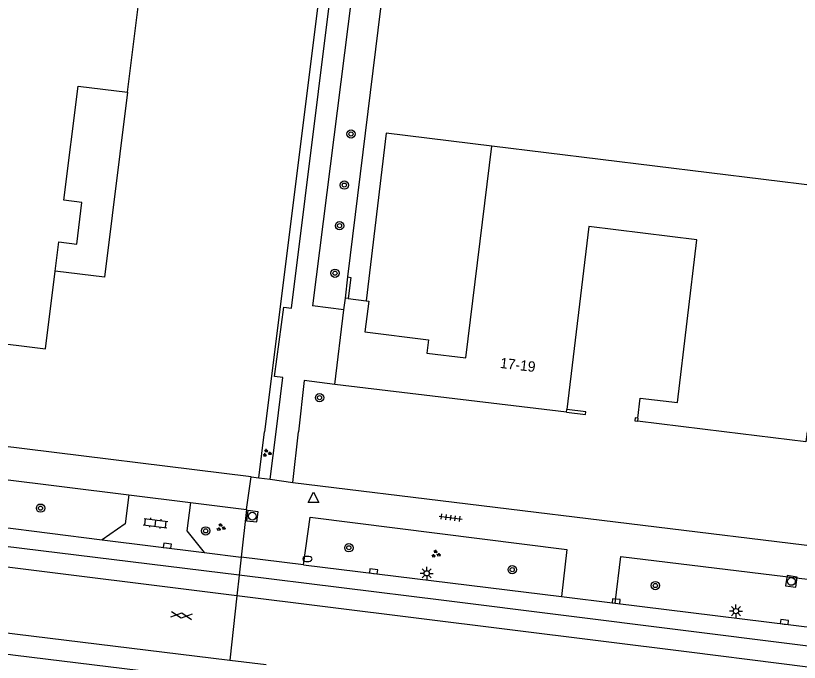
# Model space of a CAD drawing. Extents: x 131000 to 133014, y 396499 to 399001.
# Drawn here: x 131900.8 to 131976.4, y 396977.8 to 397040.1 of the extents above; entities that cross this region are included whole.
import ezdxf

# ---------------------------------------------------------------- set-up
doc = ezdxf.new("R2010")
doc.units = 0
for name, color, linetype in [('gg-afsc-hekwerk', 7, 'Continuous'), ('gg-afsc-muur', 7, 'Continuous'), ('gg-anno-huisnummerreeks BGT', 7, 'Continuous'), ('gg-bbg-gedigitaliseerde bebouwing', 7, 'Continuous'), ('gg-bbg-hoofdgebouw', 7, 'Continuous'), ('gg-bbg-luifel en loopbrug', 7, 'Continuous'), ('gg-knt-verharding', 7, 'Continuous'), ('gg-knt-verharding nz', 7, 'Continuous'), ('gt-grn-vlakafsluiter', 7, 'Continuous'), ('gt-grn-weggrens', 7, 'Continuous'), ('gt-symb-boom', 7, 'Continuous'), ('gt-symb-brandkraan', 7, 'Continuous'), ('gt-symb-gesloten verharding', 7, 'Continuous'), ('gt-symb-groenvak', 7, 'Continuous'), ('gt-symb-klinker verharding', 7, 'Continuous'), ('gt-symb-kolk', 7, 'Continuous'), ('gt-symb-lichtmast', 7, 'Continuous'), ('gt-symb-rioolschacht', 7, 'Continuous'), ('gt-symb-tegel verharding', 7, 'Continuous'), ('gt-symb-waterafsluiter', 7, 'Continuous')]:
    doc.layers.add(name, color=color, linetype=linetype)

# ---------------------------------------------------------------- blocks, each defined once
blk = doc.blocks.new('gt0-BOOM')
at = {"layer": 'gt-symb-boom'}
for radius in [0.4, 0.2]:
    blk.add_circle((0, 0), radius, dxfattribs=at)
blk = doc.blocks.new('gt0-WAFSL')
at = {"layer": 'gt-symb-waterafsluiter'}
for p, q in [((-0.5, -0.333), (0, 0.667)), ((0, 0.667), (0.5, -0.333)), ((0.5, -0.333), (-0.5, -0.333))]:
    blk.add_line(p, q, dxfattribs=at)
blk = doc.blocks.new('gt0-GRVAK')
at = {"layer": 'gt-symb-groenvak'}
for p, q in [((-0.11, 0.189), (-0.228, 0.24)), ((-0.182, 0.153), (0.088, 0.153)), ((-0.091, 0.211), (-0.156, 0.322)), ((-0.047, 0.214), (-0.047, 0.393)), ((-0.004, 0.211), (0.061, 0.322)), ((0.015, 0.189), (0.133, 0.24)), ((0.262, -0.052), (0.197, 0.059)), ((0.305, -0.049), (0.305, 0.13)), ((0.349, -0.052), (0.414, 0.059)), ((-0.245, -0.228), (-0.363, -0.177)), ((-0.318, -0.264), (-0.047, -0.264)), ((-0.226, -0.206), (-0.291, -0.095)), ((-0.183, -0.203), (-0.183, -0.024)), ((-0.139, -0.206), (-0.074, -0.095)), ((-0.12, -0.228), (-0.002, -0.177)), ((0.243, -0.074), (0.125, -0.023)), ((0.17, -0.11), (0.441, -0.11)), ((0.368, -0.074), (0.486, -0.023))]:
    blk.add_line(p, q, dxfattribs=at)
blk = doc.blocks.new('gt0-KL1')
at = {"layer": 'gt-symb-klinker verharding'}
for p, q in [((-1.15, 0.3), (1.15, 0.3)), ((-1, -0.3), (-1, 0.3)), ((-0.5, 0.3), (-0.5, 0.45)), ((0, -0.3), (0, 0.3)), ((0.5, 0.3), (0.5, 0.45)), ((1, -0.3), (1, 0.3)), ((-1.15, -0.3), (1.15, -0.3)), ((-0.5, -0.45), (-0.5, -0.3)), ((0.5, -0.45), (0.5, -0.3))]:
    blk.add_line(p, q, dxfattribs=at)
blk = doc.blocks.new('gt0-RS')
at = {"layer": 'gt-symb-rioolschacht'}
blk.add_lwpolyline([(-0.5, -0.5), (0.5, -0.5), (0.5, 0.5), (-0.5, 0.5)], close=True, dxfattribs=at)
blk.add_circle((0, 0), 0.375, dxfattribs=at)
blk = doc.blocks.new('gt0-KOLK')
at = {"layer": 'gt-symb-kolk'}
blk.add_lwpolyline([(0, 0), (0.375, 0), (0.375, 0.4), (-0.375, 0.4), (-0.375, 0), (0, 0)], dxfattribs=at)
blk = doc.blocks.new('gt0-LMAST')
at = {"layer": 'gt-symb-lichtmast'}
for p, q in [((-0.182, 0.173), (-0.447, 0.438)), ((-0.005, 0.246), (-0.005, 0.621)), ((0.172, 0.173), (0.437, 0.438)), ((-0.255, -0.004), (-0.63, -0.004)), ((-0.182, -0.181), (-0.447, -0.446)), ((-0.005, -0.254), (-0.005, -0.629)), ((0.437, -0.446), (0.172, -0.181)), ((0.245, -0.004), (0.62, -0.004))]:
    blk.add_line(p, q, dxfattribs=at)
blk.add_circle((-0.005, -0.004), 0.25, dxfattribs=at)
blk = doc.blocks.new('gt0-BR')
at = {"layer": 'gt-symb-brandkraan'}
for centre, radius, start, end in [((-0.244, 0), 0.206, 107.56694, 252.43307), ((0.599, -2.664), 3, 106.89205, 107.56694), ((0, -0.691), 0.938, 73.10799, 106.89205), ((-0.599, -2.664), 3, 72.43309, 73.10799), ((0.244, 0), 0.206, 287.56695, 72.43309), ((0.599, 2.664), 3, 252.43307, 253.10797), ((0, 0.691), 0.938, 253.10797, 286.89206), ((-0.599, 2.664), 3, 286.89206, 287.56695)]:
    blk.add_arc(centre, radius, start, end, dxfattribs=at)
blk = doc.blocks.new('gt0-TEG1')
at = {"layer": 'gt-symb-tegel verharding'}
for p, q in [((-1.125, 0), (1.125, 0)), ((-0.9, -0.25), (-0.9, 0.25)), ((-0.45, -0.25), (-0.45, 0.25)), ((0, -0.25), (0, 0.25)), ((0.45, -0.25), (0.45, 0.25)), ((0.9, -0.25), (0.9, 0.25))]:
    blk.add_line(p, q, dxfattribs=at)
blk = doc.blocks.new('gt0-GESVH1')
at = {"layer": 'gt-symb-gesloten verharding'}
for p, q in [((-0.992, -0.261), (0.008, 0.239)), ((0.008, -0.261), (-0.992, 0.239)), ((0.008, 0.239), (1.008, -0.261)), ((1.008, 0.239), (0.008, -0.261))]:
    blk.add_line(p, q, dxfattribs=at)

msp = doc.modelspace()

# ---------------------------------------------------------------- linework, layer by layer
at = {"layer": 'gg-afsc-hekwerk'}
msp.add_line((131932.903, 397064.446), (131924.856, 397000), dxfattribs=at)
msp.add_lwpolyline([(131932.89, 397014.92), (131939.73, 397070.642), (131951.59, 397069.215)], dxfattribs=at)
at = {"layer": 'gg-afsc-muur'}
for p, q in [((131932.641, 397012.873), (131932.89, 397014.92)), ((131953.989, 397001.877), (131955.8, 397001.66)), ((131960.56, 397001.06), (131960.818, 397001.028))]:
    msp.add_line(p, q, dxfattribs=at)
for points in [[(131946.783, 397027.529), (131936.59, 397028.78), (131934.65, 397012.63)], [(131932.89, 397014.92), (131933.16, 397014.88), (131932.91, 397012.84)], [(131955.8, 397001.66), (131955.83, 397001.92), (131954.02, 397002.14)], [(131960.85, 397001.29), (131960.59, 397001.32), (131960.56, 397001.06)]]:
    msp.add_lwpolyline(points, dxfattribs=at)
at = {"layer": 'gg-bbg-gedigitaliseerde bebouwing'}
for p, q in [((131980.064, 397023.446), (131946.783, 397027.529)), ((131932.91, 397012.84), (131934.65, 397012.63))]:
    msp.add_line(p, q, dxfattribs=at)
msp.add_lwpolyline([(131934.65, 397012.63), (131934.892, 397012.601), (131934.534, 397009.618), (131940.655, 397008.861), (131940.497, 397007.58), (131944.261, 397007.115), (131946.783, 397027.529)], dxfattribs=at)
at = {"layer": 'gg-bbg-hoofdgebouw'}
for p, q in [((131932.506, 397011.761), (131932.641, 397012.873)), ((131932.91, 397012.84), (131932.641, 397012.873)), ((131931.63, 397004.55), (131932.506, 397011.761)), ((131953.989, 397001.877), (131931.63, 397004.55)), ((131953.989, 397001.877), (131954.02, 397002.14)), ((131960.85, 397001.29), (131960.818, 397001.028)), ((131969.176, 397000), (131960.818, 397001.028))]:
    msp.add_line(p, q, dxfattribs=at)
for points in [[(131911.63, 397032.73), (131913.487, 397047.686), (131891.352, 397050.438)], [(131889.494, 397035.473), (131886.349, 397010.134), (131903.709, 397007.978), (131904.641, 397015.484)], [(131904.641, 397015.484), (131904.992, 397018.309), (131906.729, 397018.093), (131907.228, 397022.112), (131905.491, 397022.328), (131906.857, 397033.323), (131911.63, 397032.73)], [(131960.85, 397001.29), (131961.08, 397003.23), (131964.67, 397002.8), (131966.55, 397018.49), (131956.13, 397019.78), (131954.02, 397002.14)], [(131977.179, 397000), (131977.06, 396999.03), (131969.176, 397000)]]:
    msp.add_lwpolyline(points, dxfattribs=at)
at = {"layer": 'gg-bbg-luifel en loopbrug'}
msp.add_lwpolyline([(131911.63, 397032.73), (131909.416, 397014.891), (131904.641, 397015.484)], dxfattribs=at)
at = {"layer": 'gg-knt-verharding'}
for p, q in [((131937.41, 397075.26), (131929.484, 397012.14)), ((131932.506, 397011.761), (131929.484, 397012.14)), ((131928.666, 397004.922), (131928.111, 397000)), ((131931.63, 397004.55), (131928.666, 397004.922)), ((131828.419, 396999.672), (131909.195, 396989.576)), ((131862.805, 397000), (131911.744, 396993.913)), ((131923.541, 396995.659), (131888.328, 397000)), ((131925.4, 396995.43), (131925.96, 397000)), ((131927.56, 396995.11), (131928.111, 397000)), ((131923.541, 396995.659), (131924.309, 396995.564)), ((131924.309, 396995.564), (131925.4, 396995.43)), ((131925.4, 396995.43), (131927.56, 396995.11)), ((131927.56, 396995.11), (132000, 396986.292)), ((131911.744, 396993.913), (131917.698, 396993.172)), ((131917.698, 396993.172), (131923.1, 396992.5)), ((131923.1, 396992.5), (131922.589, 396987.915)), ((131909.195, 396989.576), (131919.015, 396988.358)), ((131919.015, 396988.358), (131922.589, 396987.915)), ((131928.599, 396987.171), (131922.589, 396987.915)), ((131928.599, 396987.171), (131953.479, 396984.104)), ((131953.479, 396984.104), (131958.659, 396983.465)), ((131958.659, 396983.465), (132000, 396978.368))]:
    msp.add_line(p, q, dxfattribs=at)
for points in [[(131925.96, 397000), (131926.6, 397005.22), (131925.81, 397005.32), (131926.69, 397012.01), (131927.45, 397011.91), (131933.966, 397064.314)], [(131911.744, 396993.913), (131911.397, 396991.114), (131909.195, 396989.576)], [(131917.698, 396993.172), (131917.358, 396990.427), (131919.015, 396988.358)], [(131928.599, 396987.171), (131929.25, 396991.77), (131954, 396988.65), (131953.479, 396984.104)], [(131958.659, 396983.465), (131959.22, 396987.96), (132000, 396983.02)]]:
    msp.add_lwpolyline(points, dxfattribs=at)
at = {"layer": 'gg-knt-verharding nz'}
msp.add_line((131921.481, 396977.976), (131924.986, 396977.548), dxfattribs=at)
for points in [[(131922.171, 396984.164), (131898.194, 396987.151), (131862.262, 396991.482), (131823.017, 396996.367), (131803.043, 396998.92), (131781.203, 397001.525), (131759.597, 397004.251), (131755.251, 397005.141), (131750.751, 397007.092), (131748.18, 397008.55), (131746.638, 397009.699)], [(131922.392, 396986.15), (131897.976, 396989.158), (131836.059, 396996.94), (131797.554, 397001.628), (131777.007, 397004.104), (131771.251, 397004.913), (131759.884, 397006.448), (131757.887, 397007.264), (131754.525, 397008.749)], [(131755.156, 396994.911), (131758.182, 396996.495), (131761.757, 396997.541), (131764.496, 396997.743), (131784.093, 396995.032), (131839.381, 396988.347), (131854.836, 396986.329), (131886.556, 396982.245), (131921.481, 396977.976)], [(131767.81, 396993.27), (131768.344, 396993.815), (131769.238, 396994.276), (131771.347, 396994.67), (131773.553, 396994.549), (131799.945, 396991.109), (131822.436, 396988.391), (131861.106, 396983.598), (131900.833, 396978.466), (131924.741, 396975.54)], [(132038.637, 396972.582), (132023.49, 396973.537), (132014.049, 396974.74), (131998.825, 396976.619), (131942.145, 396983.717), (131922.392, 396986.15)], [(132051.979, 396970.928), (132041.794, 396970.287), (132038.699, 396970.35), (132035.212, 396970.619), (132028.738, 396971.235), (132023.293, 396971.591), (131991.768, 396975.47), (131965.807, 396978.729), (131922.171, 396984.164)]]:
    msp.add_lwpolyline(points, dxfattribs=at)
at = {"layer": 'gt-grn-vlakafsluiter'}
msp.add_line((131924.309, 396995.564), (131924.856, 397000), dxfattribs=at)
at = {"layer": 'gt-grn-weggrens'}
for p, q in [((131923.1, 396992.5), (131923.541, 396995.659)), ((131922.589, 396987.915), (131922.392, 396986.15)), ((131922.392, 396986.15), (131922.171, 396984.164)), ((131922.171, 396984.164), (131921.481, 396977.976))]:
    msp.add_line(p, q, dxfattribs=at)

# ---------------------------------------------------------------- block references
at = {"layer": 'gt-symb-boom'}
for p in [(131933.188, 397028.704), (131932.538, 397023.778), (131932.079, 397019.859), (131931.639, 397015.282), (131930.149, 397003.278), (131903.233, 396992.627), (131919.167, 396990.435), (131932.979, 396988.809), (131948.738, 396986.7), (131962.549, 396985.163)]:
    msp.add_blockref('gt0-BOOM', p, dxfattribs=at)
at = {"layer": 'gt-symb-brandkraan'}
msp.add_blockref('gt0-BR', (131928.978, 396987.732), dxfattribs=at)
at = {"layer": 'gt-symb-gesloten verharding', "rotation": -7.068140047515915}
msp.add_blockref('gt0-GESVH1', (131916.82, 396982.283), dxfattribs=at)
at = {"layer": 'gt-symb-groenvak'}
msp.add_blockref('gt0-GRVAK', (131925.06, 396997.94), dxfattribs=at)
at = {"layer": 'gt-symb-groenvak', "rotation": -7.068140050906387}
for p in [(131920.637, 396990.765), (131941.358, 396988.2)]:
    msp.add_blockref('gt0-GRVAK', p, dxfattribs=at)
at = {"layer": 'gt-symb-klinker verharding', "rotation": -7.068140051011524}
msp.add_blockref('gt0-KL1', (131914.328, 396991.183), dxfattribs=at)
at = {"layer": 'gt-symb-kolk'}
for p, rotation in [((131915.444, 396988.8), -7.068140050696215), ((131935.341, 396986.34), -7.0299321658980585), ((131958.741, 396983.455), -7.0299321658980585), ((131974.975, 396981.453), -6.3802942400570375)]:
    msp.add_blockref('gt0-KOLK', p, dxfattribs=dict(at, rotation=rotation))
at = {"layer": 'gt-symb-lichtmast'}
for p in [(131940.495, 396986.343), (131970.327, 396982.702)]:
    msp.add_blockref('gt0-LMAST', p, dxfattribs=at)
at = {"layer": 'gt-symb-rioolschacht'}
for p, rotation in [((131923.669, 396991.85), -6.947410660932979), ((131975.675, 396985.562), 171.95093830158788)]:
    msp.add_blockref('gt0-RS', p, dxfattribs=dict(at, rotation=rotation))
at = {"layer": 'gt-symb-tegel verharding', "rotation": -7.068140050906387}
msp.add_blockref('gt0-TEG1', (131942.802, 396991.708), dxfattribs=at)
at = {"layer": 'gt-symb-waterafsluiter'}
msp.add_blockref('gt0-WAFSL', (131929.567, 396993.516), dxfattribs=at)

# ---------------------------------------------------------------- texts
at = {"layer": 'gg-anno-huisnummerreeks BGT'}
msp.add_text('17-19', height=1, rotation=353.2, dxfattribs=at).set_placement((131947.524, 397006.151))

doc.saveas('drawing.dxf')
